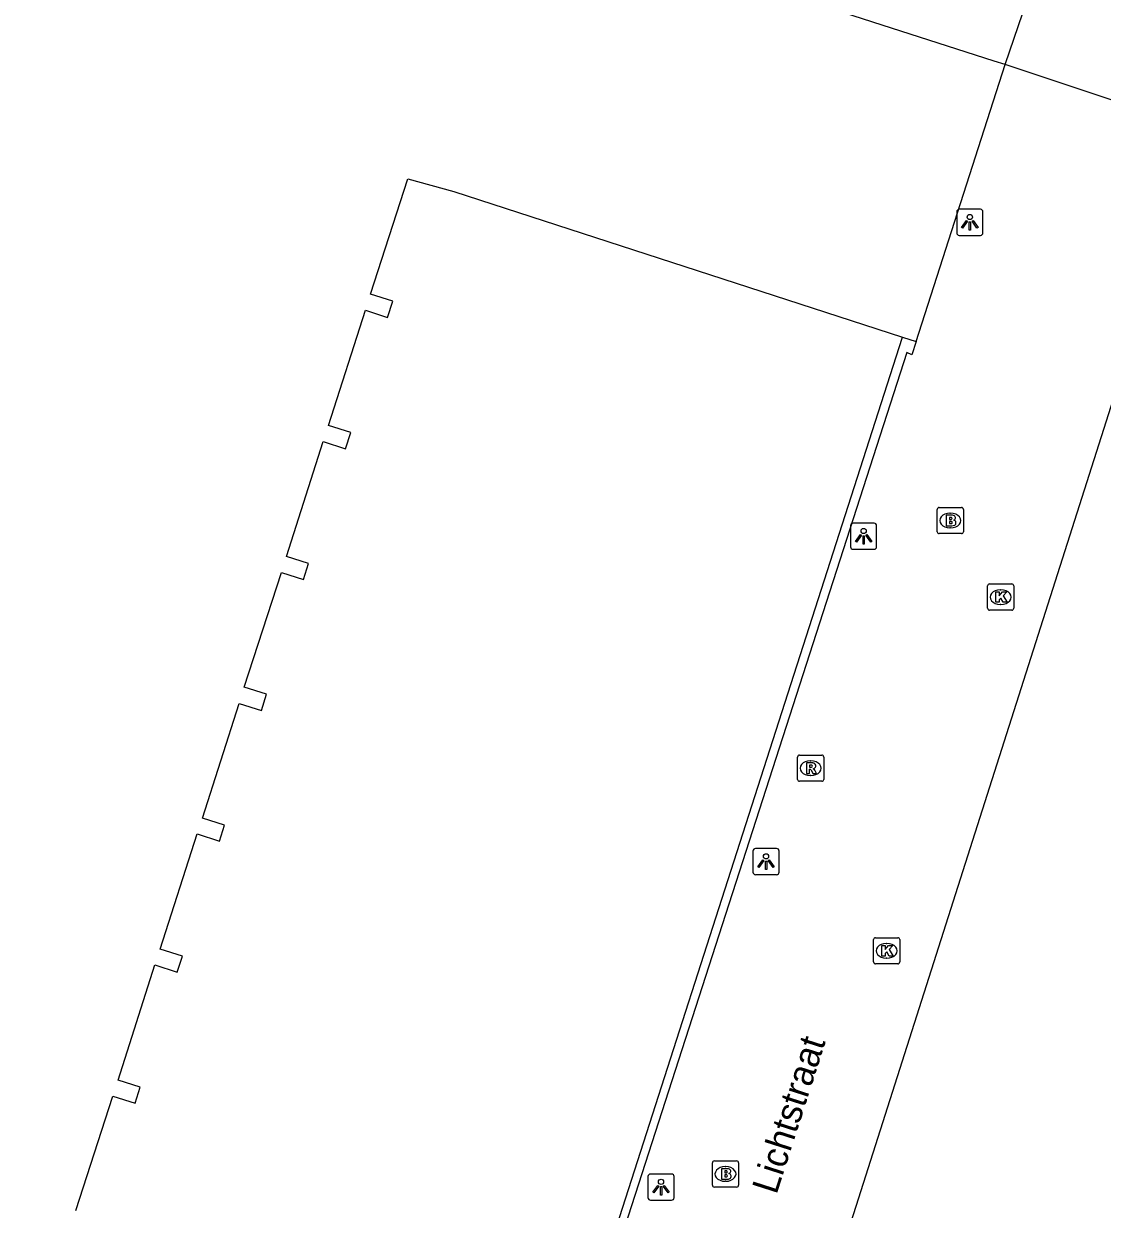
# Model space of a CAD drawing. Extents: x 160676 to 161153, y 383244 to 383713.
# Drawn here: x 160945.54 to 160986.72, y 383320.8 to 383366.07 of the extents above; entities that cross this region are included whole.
import ezdxf

# ---------------------------------------------------------------- set-up
doc = ezdxf.new("R2010")
doc.units = 0
for name, color, linetype in [('IMGEO_Brandkraan', 7, 'Continuous'), ('IMGEO_Kolk', 7, 'Continuous'), ('IMGEO_Lichtpunt', 7, 'Continuous'), ('IMGEO_Openbare_ruimte_label', 7, 'Continuous'), ('IMGEO_Pand', 7, 'Continuous'), ('IMGEO_Rijbaan_lokaal_open', 7, 'Continuous'), ('IMGEO_Rioolput', 7, 'Continuous'), ('IMGEO_Voetpad_open', 7, 'Continuous')]:
    doc.layers.add(name, color=color, linetype=linetype)

msp = doc.modelspace()

# ---------------------------------------------------------------- linework, layer by layer
at = {"layer": 'IMGEO_Brandkraan'}
for p, q in [((160980.414, 383346.672), (160980.414, 383347.524)), ((160980.489, 383347.598), (160981.341, 383347.598)), ((160980.902, 383347.378), (160980.927, 383347.378)), ((160981.415, 383347.524), (160981.415, 383346.672)), ((160981.341, 383346.598), (160980.489, 383346.598)), ((160980.925, 383346.818), (160980.9, 383346.818)), ((160971.832, 383321.719), (160971.832, 383322.571)), ((160971.907, 383322.645), (160972.759, 383322.645)), ((160972.833, 383322.571), (160972.833, 383321.719)), ((160972.32, 383322.425), (160972.345, 383322.425)), ((160972.759, 383321.645), (160971.907, 383321.645)), ((160972.343, 383321.865), (160972.318, 383321.865))]:
    msp.add_line(p, q, dxfattribs=at)
for points in [[(160980.414, 383346.672), (160980.414, 383347.524)], [(160980.489, 383347.598), (160981.341, 383347.598)], [(160981.415, 383347.524), (160981.415, 383346.672)], [(160980.762, 383347.298), (160980.762, 383346.898), (160980.975, 383346.898)], [(160980.993, 383347.298), (160980.762, 383347.298)], [(160980.941, 383347.217), (160980.887, 383347.217), (160980.887, 383347.141)], [(160980.887, 383347.141), (160980.94, 383347.141)], [(160980.949, 383347.065), (160980.887, 383347.065), (160980.887, 383346.984)], [(160980.887, 383346.984), (160980.949, 383346.984)], [(160981.341, 383346.598), (160980.489, 383346.598)], [(160971.832, 383321.719), (160971.832, 383322.571)], [(160971.907, 383322.645), (160972.759, 383322.645)], [(160972.833, 383322.571), (160972.833, 383321.719)], [(160972.18, 383322.345), (160972.18, 383321.945), (160972.393, 383321.945)], [(160972.411, 383322.345), (160972.18, 383322.345)], [(160972.359, 383322.264), (160972.305, 383322.264), (160972.305, 383322.188)], [(160972.305, 383322.188), (160972.358, 383322.188)], [(160972.367, 383322.112), (160972.305, 383322.112), (160972.305, 383322.031)], [(160972.305, 383322.031), (160972.367, 383322.031)], [(160972.759, 383321.645), (160971.907, 383321.645)]]:
    msp.add_lwpolyline(points, dxfattribs=at)
for centre, radius, start, end in [((160980.491, 383347.522), 0.0765, 91.552, 178.448), ((160980.491, 383347.522), 0.0765, 91.552, 178.448), ((160981.339, 383347.522), 0.0765, 1.552, 88.448), ((160981.339, 383347.522), 0.0765, 1.552, 88.448), ((160980.942, 383347.179), 0.0379, 267.8285, 90.9355), ((160980.95, 383347.024), 0.0404, 269.8759, 90.5077), ((160980.981, 383347.149), 0.251, 268.6676, 293.5347), ((160980.997, 383347.153), 0.145, 59.4692, 91.5367), ((160981.022, 383347.2), 0.0922, 285.5137, 58.1501), ((160981.027, 383347.008), 0.105, 301.3115, 78.989), ((160980.491, 383346.674), 0.0765, 181.552, 268.448), ((160980.491, 383346.674), 0.0765, 181.552, 268.448), ((160981.339, 383346.674), 0.0765, 271.552, 358.448), ((160981.339, 383346.674), 0.0765, 271.552, 358.448), ((160971.909, 383322.569), 0.0765, 91.552, 178.448), ((160971.909, 383322.569), 0.0765, 91.552, 178.448), ((160972.757, 383322.569), 0.0765, 1.552, 88.448), ((160972.757, 383322.569), 0.0765, 1.552, 88.448), ((160972.36, 383322.226), 0.0379, 267.8285, 90.9355), ((160972.368, 383322.071), 0.0404, 269.8759, 90.5077), ((160972.415, 383322.2), 0.145, 59.4692, 91.5367), ((160972.44, 383322.247), 0.0922, 285.5137, 58.1501), ((160972.445, 383322.055), 0.105, 301.3115, 78.989), ((160971.909, 383321.721), 0.0765, 181.552, 268.448), ((160971.909, 383321.721), 0.0765, 181.552, 268.448), ((160972.399, 383322.196), 0.251, 268.6676, 293.5347), ((160972.757, 383321.721), 0.0765, 271.552, 358.448), ((160972.757, 383321.721), 0.0765, 271.552, 358.448)]:
    msp.add_arc(centre, radius, start, end, dxfattribs=at)
for centre, major_axis, ratio, start_param, end_param in [((160980.901, 383347.098), (-0.387, 0.002), 0.722429, 4.712389, 7.853982), ((160980.926, 383347.098), (-0.39, 0.002), 0.717154, 1.570796, 4.712389), ((160972.319, 383322.145), (-0.387, 0.002), 0.722429, 4.712389, 7.853982), ((160972.344, 383322.145), (-0.39, 0.002), 0.717154, 1.570796, 4.712389)]:
    msp.add_ellipse(centre, major_axis=major_axis, ratio=ratio, start_param=start_param, end_param=end_param, dxfattribs=at)
at = {"layer": 'IMGEO_Kolk'}
for p, q in [((160982.41, 383344.675), (160983.262, 383344.675)), ((160982.335, 383343.749), (160982.335, 383344.601)), ((160982.823, 383344.455), (160982.848, 383344.455)), ((160983.336, 383344.601), (160983.336, 383343.749)), ((160982.846, 383343.895), (160982.821, 383343.895)), ((160983.262, 383343.675), (160982.41, 383343.675)), ((160977.983, 383330.241), (160977.983, 383331.093)), ((160978.058, 383331.167), (160978.91, 383331.167)), ((160978.984, 383331.093), (160978.984, 383330.241)), ((160978.471, 383330.947), (160978.496, 383330.947)), ((160978.91, 383330.167), (160978.058, 383330.167)), ((160978.494, 383330.387), (160978.469, 383330.387))]:
    msp.add_line(p, q, dxfattribs=at)
for points in [[(160982.41, 383344.675), (160983.262, 383344.675)], [(160982.335, 383343.749), (160982.335, 383344.601)], [(160982.656, 383344.375), (160982.779, 383344.375), (160982.779, 383344.224), (160982.909, 383344.375), (160983.073, 383344.375), (160982.927, 383344.224), (160983.08, 383343.975), (160982.928, 383343.975), (160982.843, 383344.139), (160982.779, 383344.072), (160982.779, 383343.975), (160982.656, 383343.975), (160982.656, 383344.375)], [(160983.336, 383344.601), (160983.336, 383343.749)], [(160983.262, 383343.675), (160982.41, 383343.675)], [(160977.983, 383330.241), (160977.983, 383331.093)], [(160978.058, 383331.167), (160978.91, 383331.167)], [(160978.984, 383331.093), (160978.984, 383330.241)], [(160978.304, 383330.867), (160978.427, 383330.867), (160978.427, 383330.716), (160978.557, 383330.867), (160978.721, 383330.867), (160978.575, 383330.716), (160978.728, 383330.467), (160978.576, 383330.467), (160978.491, 383330.631), (160978.427, 383330.564), (160978.427, 383330.467), (160978.304, 383330.467), (160978.304, 383330.867)], [(160978.91, 383330.167), (160978.058, 383330.167)]]:
    msp.add_lwpolyline(points, dxfattribs=at)
for centre, start, end in [((160982.412, 383344.599), 91.552, 178.448), ((160982.412, 383344.599), 91.552, 178.448), ((160983.26, 383344.599), 1.552, 88.448), ((160983.26, 383344.599), 1.552, 88.448), ((160982.412, 383343.751), 181.552, 268.448), ((160982.412, 383343.751), 181.552, 268.448), ((160983.26, 383343.751), 271.552, 358.448), ((160983.26, 383343.751), 271.552, 358.448), ((160978.06, 383331.091), 91.552, 178.448), ((160978.06, 383331.091), 91.552, 178.448), ((160978.908, 383331.091), 1.552, 88.448), ((160978.908, 383331.091), 1.552, 88.448), ((160978.06, 383330.243), 181.552, 268.448), ((160978.06, 383330.243), 181.552, 268.448), ((160978.908, 383330.243), 271.552, 358.448), ((160978.908, 383330.243), 271.552, 358.448)]:
    msp.add_arc(centre, 0.0765, start, end, dxfattribs=at)
for centre, major_axis, ratio, start_param, end_param in [((160982.822, 383344.175), (-0.387, 0.002), 0.722429, 4.712389, 7.853982), ((160982.847, 383344.175), (-0.39, 0.002), 0.717154, 1.570796, 4.712389), ((160978.47, 383330.667), (-0.387, 0.002), 0.722429, 4.712389, 7.853982), ((160978.495, 383330.667), (-0.39, 0.002), 0.717154, 1.570796, 4.712389)]:
    msp.add_ellipse(centre, major_axis=major_axis, ratio=ratio, start_param=start_param, end_param=end_param, dxfattribs=at)
at = {"layer": 'IMGEO_Lichtpunt'}
for p, q in [((160981.161, 383358.89), (160981.161, 383358.083)), ((160981.161, 383358.89), (160981.161, 383358.083)), ((160982.063, 383358.985), (160981.255, 383358.985)), ((160982.063, 383358.985), (160981.255, 383358.985)), ((160982.157, 383358.083), (160982.157, 383358.89)), ((160982.157, 383358.083), (160982.157, 383358.89)), ((160981.255, 383357.989), (160982.063, 383357.989)), ((160981.255, 383357.989), (160982.063, 383357.989)), ((160978.009, 383346.997), (160977.201, 383346.997)), ((160978.009, 383346.997), (160977.201, 383346.997)), ((160977.107, 383346.902), (160977.107, 383346.095)), ((160977.107, 383346.902), (160977.107, 383346.095)), ((160978.103, 383346.095), (160978.103, 383346.902)), ((160978.103, 383346.095), (160978.103, 383346.902)), ((160977.201, 383346.001), (160978.009, 383346.001)), ((160977.201, 383346.001), (160978.009, 383346.001)), ((160973.382, 383334.476), (160973.382, 383333.669)), ((160973.382, 383334.476), (160973.382, 383333.669)), ((160974.284, 383334.571), (160973.476, 383334.571)), ((160974.284, 383334.571), (160973.476, 383334.571)), ((160974.378, 383333.669), (160974.378, 383334.476)), ((160974.378, 383333.669), (160974.378, 383334.476)), ((160973.476, 383333.575), (160974.284, 383333.575)), ((160973.476, 383333.575), (160974.284, 383333.575)), ((160969.374, 383322.046), (160969.374, 383321.239)), ((160969.374, 383322.046), (160969.374, 383321.239)), ((160970.276, 383322.141), (160969.468, 383322.141)), ((160970.276, 383322.141), (160969.468, 383322.141)), ((160970.37, 383321.239), (160970.37, 383322.046)), ((160970.37, 383321.239), (160970.37, 383322.046)), ((160969.468, 383321.145), (160970.276, 383321.145)), ((160969.468, 383321.145), (160970.276, 383321.145))]:
    msp.add_line(p, q, dxfattribs=at)
for points in [[(160981.535, 383358.554), (160981.574, 383358.526), (160981.386, 383358.264), (160981.348, 383358.291), (160981.535, 383358.554)], [(160981.637, 383358.506), (160981.684, 383358.506), (160981.684, 383358.184), (160981.637, 383358.184), (160981.637, 383358.506)], [(160981.747, 383358.526), (160981.785, 383358.553), (160981.972, 383358.291), (160981.933, 383358.263), (160981.747, 383358.526)], [(160977.481, 383346.566), (160977.52, 383346.538), (160977.332, 383346.276), (160977.294, 383346.303), (160977.481, 383346.566)], [(160977.583, 383346.518), (160977.63, 383346.518), (160977.63, 383346.196), (160977.583, 383346.196), (160977.583, 383346.518)], [(160977.693, 383346.538), (160977.731, 383346.565), (160977.918, 383346.303), (160977.879, 383346.275), (160977.693, 383346.538)], [(160973.756, 383334.14), (160973.795, 383334.112), (160973.607, 383333.85), (160973.569, 383333.877), (160973.756, 383334.14)], [(160973.858, 383334.092), (160973.905, 383334.092), (160973.905, 383333.77), (160973.858, 383333.77), (160973.858, 383334.092)], [(160973.968, 383334.112), (160974.006, 383334.139), (160974.193, 383333.877), (160974.154, 383333.849), (160973.968, 383334.112)], [(160969.748, 383321.71), (160969.787, 383321.682), (160969.599, 383321.42), (160969.561, 383321.447), (160969.748, 383321.71)], [(160969.85, 383321.662), (160969.897, 383321.662), (160969.897, 383321.34), (160969.85, 383321.34), (160969.85, 383321.662)], [(160969.96, 383321.682), (160969.998, 383321.709), (160970.185, 383321.447), (160970.146, 383321.419), (160969.96, 383321.682)]]:
    msp.add_lwpolyline(points, dxfattribs=at)
for centre in [(160981.66, 383358.688), (160977.606, 383346.7), (160973.881, 383334.274), (160969.873, 383321.844)]:
    msp.add_circle(centre, 0.0994, dxfattribs=at)
for centre, start, end in [((160981.255, 383358.89), 90, 180), ((160981.255, 383358.89), 90, 180), ((160982.063, 383358.89), 0, 90), ((160982.063, 383358.89), 0, 90), ((160981.255, 383358.083), 180, 270), ((160981.255, 383358.083), 180, 270), ((160982.063, 383358.083), 270, 0), ((160982.063, 383358.083), 270, 360), ((160977.201, 383346.902), 90, 180), ((160977.201, 383346.902), 90, 180), ((160978.009, 383346.902), 0, 90), ((160978.009, 383346.902), 0, 90), ((160977.201, 383346.095), 180, 270), ((160977.201, 383346.095), 180, 270), ((160978.009, 383346.095), 270, 0), ((160978.009, 383346.095), 270, 360), ((160973.476, 383334.476), 90, 180), ((160973.476, 383334.476), 90, 180), ((160974.284, 383334.476), 0, 90), ((160974.284, 383334.476), 0, 90), ((160973.476, 383333.669), 180, 270), ((160973.476, 383333.669), 180, 270), ((160974.284, 383333.669), 270, 0), ((160974.284, 383333.669), 270, 360), ((160969.468, 383322.046), 90, 180), ((160969.468, 383322.046), 90, 180), ((160970.276, 383322.046), 0, 90), ((160970.276, 383322.046), 0, 90), ((160969.468, 383321.239), 180, 270), ((160969.468, 383321.239), 180, 270), ((160970.276, 383321.239), 270, 0), ((160970.276, 383321.239), 270, 360)]:
    msp.add_arc(centre, 0.0946, start, end, dxfattribs=at)
at = {"layer": 'IMGEO_Pand'}
for points in [[(160983.014, 383364.509), (160982.591, 383364.645), (160954.685, 383373.627), (160954.237, 383372.205), (160949.044, 383373.871), (160949.493, 383375.293), (160945.544, 383376.569)], [(160979.608, 383353.93), (160983.014, 383364.509)], [(160988.884, 383362.56), (160988.097, 383360.087), (160989.634, 383359.598), (160976.293, 383317.706), (160974.69, 383318.217), (160973.542, 383314.614), (160975.14, 383314.105), (160972.968, 383307.284), (160976.986, 383306.005), (160976.237, 383303.65), (160982.34, 383300.282), (160989.622, 383299.281), (160990.405, 383301.74), (160994.422, 383300.461)], [(160947.536, 383320.743), (160948.948, 383325.121), (160949.796, 383324.85), (160949.993, 383325.461), (160949.145, 383325.732), (160950.551, 383330.128), (160951.399, 383329.857), (160951.605, 383330.462), (160950.757, 383330.733), (160952.167, 383335.128), (160953.015, 383334.857), (160953.213, 383335.462), (160952.365, 383335.733), (160953.771, 383340.116), (160954.619, 383339.845), (160954.813, 383340.467), (160953.965, 383340.738), (160955.38, 383345.115), (160956.228, 383344.844), (160956.42, 383345.459), (160955.572, 383345.73), (160956.976, 383350.112), (160957.832, 383349.838), (160958.03, 383350.459), (160957.182, 383350.73), (160958.588, 383355.129), (160959.436, 383354.858), (160959.633, 383355.477), (160958.785, 383355.748), (160960.201, 383360.148), (160961.959, 383359.669), (160979.089, 383354.099)], [(160979.089, 383354.099), (160979.608, 383353.93)]]:
    msp.add_lwpolyline(points, dxfattribs=at)
at = {"layer": 'IMGEO_Rijbaan_lokaal_open'}
for points in [[(160983.014, 383364.509), (160983.844, 383366.986)], [(160988.884, 383362.56), (160983.014, 383364.509)], [(160979.608, 383353.93), (160979.448, 383353.431), (160979.25, 383353.51), (160964.138, 383306.646), (160963.969, 383306.082), (160964.19, 383306.014), (160963.499, 383303.848), (160992.588, 383294.531)]]:
    msp.add_lwpolyline(points, dxfattribs=at)
at = {"layer": 'IMGEO_Rioolput'}
for p, q in [((160975.082, 383337.215), (160975.082, 383338.067)), ((160975.157, 383338.141), (160976.009, 383338.141)), ((160975.57, 383337.921), (160975.595, 383337.921)), ((160976.083, 383338.067), (160976.083, 383337.215)), ((160976.009, 383337.141), (160975.157, 383337.141)), ((160975.593, 383337.361), (160975.568, 383337.361))]:
    msp.add_line(p, q, dxfattribs=at)
for points in [[(160975.082, 383337.215), (160975.082, 383338.067)], [(160975.157, 383338.141), (160976.009, 383338.141)], [(160976.083, 383338.067), (160976.083, 383337.215)], [(160975.671, 383337.839), (160975.419, 383337.841), (160975.419, 383337.441)], [(160975.419, 383337.441), (160975.543, 383337.441), (160975.543, 383337.603), (160975.554, 383337.603)], [(160975.597, 383337.76), (160975.543, 383337.76), (160975.543, 383337.679)], [(160975.543, 383337.679), (160975.595, 383337.679)], [(160975.601, 383337.574), (160975.672, 383337.441), (160975.812, 383337.441), (160975.747, 383337.567)], [(160976.009, 383337.141), (160975.157, 383337.141)]]:
    msp.add_lwpolyline(points, dxfattribs=at)
for centre, radius, start, end in [((160975.159, 383338.065), 0.0765, 91.552, 178.448), ((160975.159, 383338.065), 0.0765, 91.552, 178.448), ((160976.007, 383338.065), 0.0765, 1.552, 88.448), ((160976.007, 383338.065), 0.0765, 1.552, 88.448), ((160975.553, 383337.55), 0.0533, 26.0293, 88.6989), ((160975.579, 383337.868), 0.19, 274.7715, 282.9687), ((160975.603, 383337.664), 0.0964, 77.0061, 93.1865), ((160975.617, 383337.721), 0.0378, 276.6634, 79.6772), ((160975.67, 383337.729), 0.109, 350.3612, 89.416), ((160975.668, 383337.729), 0.112, 277.5842, 350.9817), ((160975.652, 383337.514), 0.108, 29.5134, 73.7905), ((160975.159, 383337.217), 0.0765, 181.552, 268.448), ((160975.159, 383337.217), 0.0765, 181.552, 268.448), ((160976.007, 383337.217), 0.0765, 271.552, 358.448), ((160976.007, 383337.217), 0.0765, 271.552, 358.448)]:
    msp.add_arc(centre, radius, start, end, dxfattribs=at)
for centre, major_axis, ratio, start_param, end_param in [((160975.569, 383337.641), (-0.387, 0.002), 0.722429, 4.712389, 7.853982), ((160975.594, 383337.641), (-0.39, 0.002), 0.717154, 1.570796, 4.712389)]:
    msp.add_ellipse(centre, major_axis=major_axis, ratio=ratio, start_param=start_param, end_param=end_param, dxfattribs=at)
at = {"layer": 'IMGEO_Voetpad_open'}
msp.add_lwpolyline([(160962.889, 383303.693), (160979.089, 383354.099)], dxfattribs=at)

# ---------------------------------------------------------------- texts
at = {"layer": 'IMGEO_Openbare_ruimte_label'}
msp.add_text('Lichtstraat', height=1, rotation=72.2357, dxfattribs=at).set_placement((160974.278, 383321.327))

doc.saveas('drawing.dxf')
